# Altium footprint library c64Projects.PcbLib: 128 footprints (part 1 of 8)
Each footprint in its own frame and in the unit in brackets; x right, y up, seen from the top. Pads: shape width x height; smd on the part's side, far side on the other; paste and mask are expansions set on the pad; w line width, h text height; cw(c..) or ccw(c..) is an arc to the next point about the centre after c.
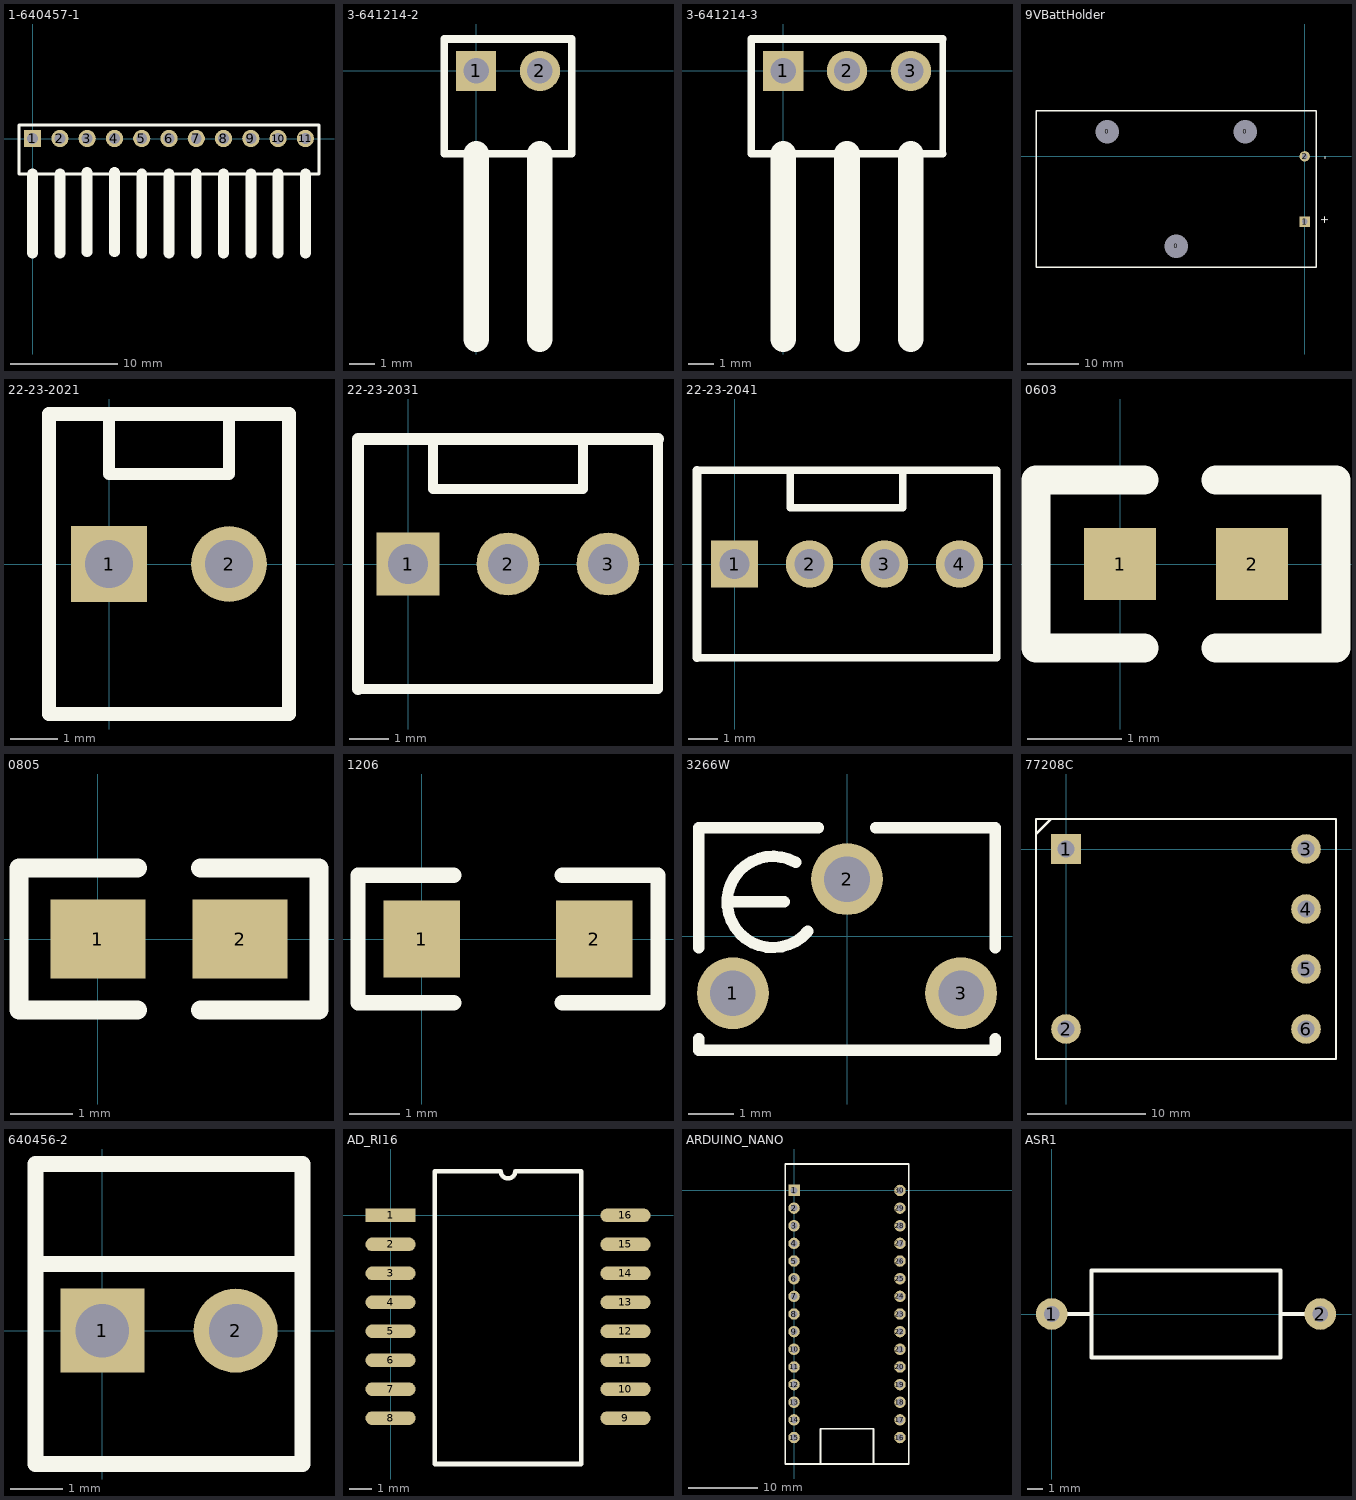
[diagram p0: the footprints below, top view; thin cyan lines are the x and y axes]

## 1-640457-1 [mil]
pads (11):
  rect 63x63 hole 40: 1(0,0)
  round 63 hole 40: 2(100,0) 3(200,0) 4(300,0) 5(400,0) 6(500,0) 7(600,0) 8(700,0) 9(800,0) 10(900,0) 11(1000,0)
Top Overlay:
  lines w10: 0,-320 0,-130 ; 100,-320 100,-130 ; 200,-315 200,-125 ; 300,-315 300,-125 ; 400,-320 400,-130 ; 500,-320 500,-130 ; 600,-320 600,-130 ; 700,-320 700,-130 ; 800,-320 800,-130 ; 900,-320 900,-130
  lines w12: -50,-130 1050,-130 1050,50 -50,50 -50,-130
  lines w40: 0,-420 0,-130 ; 100,-420 100,-130 ; 200,-415 200,-125 ; 300,-415 300,-125 ; 400,-420 400,-130 ; 500,-420 500,-130 ; 600,-420 600,-130 ; 700,-420 700,-130 ; 800,-420 800,-130 ; 900,-420 900,-130 ; 1000,-420 1000,-130

## 3-641214-2 [mil]
pads (2):
  rect 63x63 hole 40: 1(0,0)
  round 63 hole 40: 2(100,0)
Top Overlay:
  lines w10: 0,-320 0,-130 ; 100,-320 100,-130
  lines w12: -50,-130 -50,50 150,50 150,-130 -50,-130
  lines w40: 0,-420 0,-130 ; 100,-420 100,-130

## 3-641214-3 [mil]
pads (3):
  rect 63x63 hole 40: 1(0,0)
  round 63 hole 40: 2(100,0) 3(200,0)
Top Overlay:
  lines w10: 0,-320 0,-130 ; 100,-320 100,-130 ; 250,-130 250,50
  lines w12: 250,-130 -50,-130 -50,50 250,50
  lines w40: 0,-420 0,-130 ; 100,-420 100,-130 ; 200,-420 200,-130

## 9VBattHolder [mil]
pads (5):
  round 63 hole 180 unplated: 0(-1515,190) 0(-985,-690) 0(-455,190)
  rect 80x80 hole 45: 1(0,-500)
  round 80 hole 45: 2(0,0)
Top Overlay:
  lines w10: -2060,-850 90,-850 90,350 -2060,350 -2060,-850
  text "-" at 180,-25 h60
  text "+" at 180,-520 h60

## 22-23-2021 [mil]
pads (2):
  rect 63x63 hole 40: 1(0,0)
  round 63 hole 40: 2(100,0)
Top Overlay:
  lines w10: 0,125 0,75 100,75 100,125
  lines w12: -50,-125 -50,125 150,125 150,-125 -50,-125
3D body: height 630, standoff 0, extent -50,-125 150,125

## 22-23-2031 [mil]
pads (3):
  rect 63x63 hole 40: 1(0,0)
  round 63 hole 40: 2(100,0) 3(200,0)
Top Overlay:
  lines w10: -50,-125 250,-125 250,125 ; 25,125 25,75 175,75 175,125
  lines w12: -50,-125 -50,125 250,125
3D body: height 630, standoff 0, extent -50,-125 250,125

## 22-23-2041 [mil]
pads (4):
  rect 63x63 hole 40: 1(0,0)
  round 63 hole 40: 2(100,0) 3(200,0) 4(300,0)
Top Overlay:
  lines w10: -50,-125 350,-125 350,125 -50,125 ; 74.21,125 74.21,75 224.21,75 224.21,125
  lines w12: -50,-125 -50,125
3D body: height 630, standoff 0, extent -50,-125 350,125

## 0603 [mil]
pads (2):
  rect 30x30 smd: 1(0,0) 2(55,0)
Top Overlay:
  lines w12: 10,-35 -35,-35 -35,35 10,35 ; 40,-35 90,-35 90,35 40,35

## 0805 [mil]
pads (2):
  rect 60x50 smd: 1(0,0) 2(90,0)
Top Overlay:
  lines w12: 25,-45 -50,-45 -50,45 25,45 ; 65,-45 140,-45 140,45 65,45

## 1206 [mil]
pads (2):
  rect 60x60 smd: 1(0,0) 2(135,0)
Top Overlay:
  lines w12: 25,-50 -50,-50 -50,50 25,50 ; 110,-50 185,-50 185,50 110,50

## 3266W [mil]
pads (3):
  round 63 hole 40: 1(-100,-50) 2(0,50) 3(100,-50)
Top Overlay:
  lines w10: -130,-90 -130,-100 130,-100 130,-90 ; -130,-10 -130,95 -25,95 ; -105,30 -55,30 ; -45,64.64 ccw(c-65,30) -34.36,4.29 ; 25,95 130,95 130,-10

## 77208C [mm]
pads (6):
  rect 2.5x2.5 hole 1.4: 1(0,0)
  round 2.5 hole 1.4: 2(0,-15.24) 3(20.32,0) 4(20.32,-5.08) 5(20.32,-10.16) 6(20.32,-15.24)
Top Overlay:
  lines w0.2: -2.54,1.27 -1.27,2.54 ; -2.54,-17.78 -2.54,2.54 22.86,2.54 22.86,-17.78 -2.54,-17.78

## 640456-2 [mil]
pads (2):
  rect 63x63 hole 40: 1(0,0)
  round 63 hole 40: 2(100,0)
Top Overlay:
  lines w12: -50,50 150,50 ; -50,-100 -50,125 150,125 150,-100 -50,-100

## AD_RI16 [mm]
pads (16):
  rect 2.2x0.6 smd: 1(0,0)
  oval 2.2x0.6 smd: 2(0,-1.27) 3(0,-2.54) 4(0,-3.81) 5(0,-5.08) 6(0,-6.35) 7(0,-7.62) 8(0,-8.89) 9(10.3,-8.89) 10(10.3,-7.62) 11(10.3,-6.35) 12(10.3,-5.08) 13(10.3,-3.81) 14(10.3,-2.54) 15(10.3,-1.27) 16(10.3,0)
Top Overlay:
  lines w0.2: 1.935,-10.9 8.365,-10.9 8.365,1.935 5.467,1.935 cw(c5.15,1.935) 4.832,1.935 1.935,1.935 1.935,-10.9

## ARDUINO_NANO [mil]
pads (30):
  rect 65x65 hole 40: 1(0,0)
  round 65 hole 40: 2(0,-100) 3(0,-200) 4(0,-300) 5(0,-400) 6(0,-500) 7(0,-600) 8(0,-700) 9(0,-800) 10(0,-900) 11(0,-1000) 12(0,-1100) 13(0,-1200) 14(0,-1300) 15(0,-1400) 16(600,-1400) 17(600,-1300) 18(600,-1200) 19(600,-1100) 20(600,-1000) 21(600,-900) 22(600,-800) 23(600,-700) 24(600,-600) 25(600,-500) 26(600,-400) 27(600,-300) 28(600,-200) 29(600,-100) 30(600,0)
Top Overlay:
  lines w10: 150,-1550 150,-1350 450,-1350 450,-1550 ; -50,-1550 650,-1550 650,150 -50,150 -50,-1550

## ASR1 [mm]
pads (2):
  round 2 hole 1: 1(0,0) 2(17,0)
Top Overlay:
  lines w0.254: 0,0 2.5,0 ; 14.5,0 17,0 ; 2.5,-2.75 2.5,2.75 14.5,2.75 14.5,-2.75 2.5,-2.75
